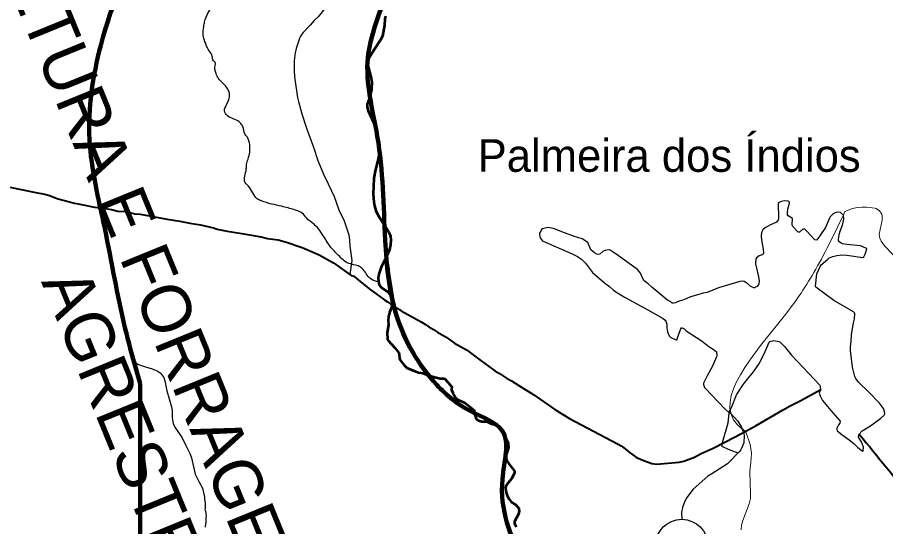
# Model space of a CAD drawing. Extents: x -1643653 to 4543381, y 1624270 to 13878484.
# Drawn here: x 748641 to 761950, y 8955606 to 8963412 of the extents above; entities that cross this region are included whole.
import ezdxf
from ezdxf.enums import TextEntityAlignment as Align

# ---------------------------------------------------------------- set-up
doc = ezdxf.new("R2010")
doc.units = 0
doc.header["$LTSCALE"] = 200
for name, color, linetype, lineweight in [('12', 7, 'Continuous', 25), ('14', 7, 'Continuous', 13), ('21', 7, 'Continuous', 25), ('24', 7, 'Continuous', 25), ('26', 7, 'Continuous', 106), ('28', 7, 'Continuous', 53), ('48', 7, 'Continuous', 25), ('60', 7, 'Continuous', 13), ('9', 7, 'Continuous', 90)]:
    doc.layers.add(name, color=color, linetype=linetype, lineweight=lineweight)
doc.layers.add('41', color=7, linetype='Continuous')
doc.layers.add('42', color=7, linetype='Continuous')

msp = doc.modelspace()

# ---------------------------------------------------------------- linework, layer by layer
at = {"layer": '12'}
for points in [[(753459.3, 8963663.9), (753375.2, 8963570.6), (753254.1, 8963422.1), (753189.6, 8963361.6), (753131.1, 8963293.6), (753017.7, 8963172.8), (752982.1, 8963123.5), (752970.7, 8963101.1), (752914.6, 8962932.2), (752900.9, 8962868.1), (752884.4, 8962747.8), (752884.2, 8962579.2), (752893.6, 8962459.8), (752918.2, 8962289)], [(752918.2, 8962289), (752933.3, 8962184.9), (752947.7, 8962120.1), (752999.2, 8961934.7), (753071.9, 8961715.6), (753180.7, 8961424), (753248.1, 8961217.1), (753248.1, 8961217.1), (753333.6, 8961006.6), (753405.8, 8960861.1), (753494.8, 8960666.1), (753525.5, 8960579.3)], [(753525.5, 8960579.3), (753567.3, 8960461.2), (753647.9, 8960293.1), (753719.6, 8960078), (753729.9, 8960000.8), (753736.5, 8959906), (753766.3, 8959686.5), (753736.3, 8959470.4)], [(759689.9, 8956732.7), (759543.3, 8956787), (759453.4, 8956827.9), (759441.1, 8956839.4), (759450.5, 8956898), (759538.2, 8957195.8), (759549.6, 8957346.3), (759553.3, 8957357.9), (759571, 8957344.3), (759680.6, 8957229.9), (759737, 8957142.1), (759777.6, 8957031.5), (759780.6, 8957004.8), (759774.7, 8956889.8), (759729.9, 8956785.1), (759706.9, 8956753.4), (759526.3, 8956568.6), (759344.8, 8956450.4), (759284.8, 8956417.4), (759226.1, 8956377.1), (758999, 8956178.4), (758931.1, 8956094.6), (758894, 8956037.2), (758861.3, 8955972.4), (758835.9, 8955899.8), (758821.1, 8955826.8), (758825.4, 8955718.1)]]:
    msp.add_lwpolyline(points, dxfattribs=at)
at = {"layer": '12', "lineweight": 40}
for points in [[(747824.8, 8960950.1), (748696.8, 8960775.7), (748951, 8960720.9), (749061.5, 8960701.6), (749146.4, 8960677), (749208.9, 8960650.1), (749264.1, 8960631.6), (749514.7, 8960562.8), (749573.6, 8960554.1), (749824.1, 8960500.3), (749993.7, 8960480.2), (750082, 8960465.4), (750181.5, 8960442.6), (750295.8, 8960435.7), (750443.2, 8960399.6), (750522, 8960394.7), (750939.1, 8960317.4), (751130.9, 8960287.1), (751285.6, 8960255.2), (751447.8, 8960232), (751646.7, 8960184), (751702.1, 8960166.7), (751856.8, 8960132.2), (752079.6, 8960098.7), (752168.1, 8960083)], [(752168.1, 8960083), (752376.2, 8960046), (752473.7, 8960024.1), (752636.8, 8960000.4), (752768, 8959966), (753007.9, 8959884.9), (753265, 8959774.4), (753487.3, 8959648.4), (753758.2, 8959455.5), (753784.2, 8959450.7), (753798.9, 8959443.4), (753866.8, 8959388.1)], [(753866.8, 8959388.1), (754029.7, 8959255.4), (754273.1, 8959074.6), (754315.3, 8959050.4), (754424.8, 8958977.4), (754499, 8958935.4), (754521.9, 8958913.6), (754830.4, 8958745.4), (754896.1, 8958704.8), (754948.1, 8958666.3), (755022.1, 8958627.1), (755080.2, 8958588.1), (755212.9, 8958510.5), (755342.6, 8958419.2), (755526.8, 8958316.3), (755751.2, 8958147.5)], [(755751.2, 8958147.5), (755862.2, 8958064), (755958, 8957996.2), (756032.6, 8957954.2), (756137.7, 8957884), (756214, 8957842.6), (756328.1, 8957767.5), (756559.2, 8957627.5), (756879.8, 8957401.3), (757104, 8957264.6), (757287.1, 8957167.7), (757840.4, 8956875)], [(759805, 8957070.3), (759963.8, 8957157.4), (760368.2, 8957393.4), (760487, 8957457.4), (760649.4, 8957537.9), (760959, 8957710.3)], [(757840.4, 8956875), (757898, 8956844.5), (757957.3, 8956800.7), (758017.3, 8956746), (758132.8, 8956665.6), (758252.6, 8956612), (758364.7, 8956572), (758441.3, 8956562.7), (758786.4, 8956593.9), (758858.3, 8956611.9), (759022.3, 8956672.3), (759120.5, 8956724.4), (759308, 8956809.8), (759644.5, 8956982.5), (759805, 8957070.3)]]:
    msp.add_lwpolyline(points, dxfattribs=at)
msp.add_spline([(761549.2, 8957020.4), (762383.1, 8955993.9), (763257, 8954902.9), (764214.4, 8953717.3), (766168.2, 8951324.4), (767086.6, 8950171.6), (770317.8, 8946184.2), (771971, 8944146), (773006.3, 8942876.2), (773223.4, 8942642.3), (773373.7, 8942274.8), (774008.3, 8940921.5), (774359, 8940136.3), (774475.8, 8939919.1), (774642.8, 8939785.5), (774893.3, 8939668.5), (775511.2, 8939484.7), (775928.6, 8939267.5), (776078.9, 8939184), (776379.5, 8938916.7), (776680.1, 8938749.6), (776830.4, 8938582.6), (777398.1, 8938348.7), (777899.1, 8938231.7), (778550.4, 8938482.3), (779134.8, 8938866.6), (779452.1, 8939250.8), (779569, 8939384.5), (779685.9, 8939351.1), (779852.9, 8939217.4), (780086.7, 8939217.4), (780604.3, 8939451.3), (781055.2, 8939618.4), (781439.3, 8939618.4), (781823.3, 8939518.1), (782090.5, 8939401.2), (782290.9, 8939367.8), (782524.7, 8939518.1), (782858.7, 8939618.4), (783192.6, 8939651.8), (783509.9, 8939818.9), (783910.7, 8940119.6), (784278.1, 8940336.8), (784625.2, 8940434.5)], degree=3, dxfattribs=at)
at = {"layer": '14'}
for points in [[(762539, 8959785.5), (762526.5, 8959782.1), (762447.5, 8959737.2), (762371.9, 8959688.1), (762188, 8959687.4), (762169, 8959695.8), (762058.2, 8959775.3), (761932.6, 8959909.4), (761880.9, 8959981.3), (761863.6, 8960025), (761852.7, 8960090.2), (761896.3, 8960301.7), (761898.2, 8960370.1), (761891.8, 8960394.3), (761858.6, 8960446.3), (761803.1, 8960482.1), (761785, 8960487.6), (761657.6, 8960503.3), (761588.8, 8960503.3), (761520, 8960497.3), (761442.8, 8960481.4), (761326.7, 8960433.8), (761317.3, 8960424.7), (761303.1, 8960378.2)], [(759805, 8957070.3), (759809.7, 8957060.9), (759876.2, 8956866.7), (759896, 8956733.5), (759886, 8956587.7), (759873.4, 8956514.6), (759867.3, 8956445.9), (759879.8, 8956106.2), (759877.3, 8956037.4), (759858.6, 8955956.3), (759761.5, 8955697.4), (759741.8, 8955628.8), (759734.4, 8955555.9)]]:
    msp.add_lwpolyline(points, dxfattribs=at)
msp.add_spline([(761326.7, 8960433.8), (760878.8, 8959550), (760374.9, 8958805.9), (759682, 8957166.3), (759809.7, 8957060.9)], degree=3, dxfattribs=at)
at = {"layer": '21'}
for points in [[(760406.9, 8960599.4), (760351.2, 8960587.4), (760306.3, 8960567.9), (760304.1, 8960553.3), (760309.9, 8960343.7), (760307.6, 8960319.4), (760302.3, 8960306.5), (760277, 8960272.3), (760173.9, 8960227.9), (760102, 8960186.9), (760066.3, 8960155.5), (760048.5, 8960114.9), (760043.8, 8960055.7), (760047.2, 8959999.8), (760070.9, 8959859.8), (760077.3, 8959796.6), (760071.9, 8959782.9), (760055.5, 8959771.5), (760010.4, 8959755.9), (759970.5, 8959727.7), (759962.7, 8959712), (759957.3, 8959636.2), (760000.3, 8959433.2), (760011.1, 8959366.6), (760007.5, 8959329.7), (759980.1, 8959288.4), (759957.5, 8959276), (759943.8, 8959263.8), (759943.8, 8959263.8), (759931.4, 8959264.6), (759884.8, 8959286.2), (759838.1, 8959329.8), (759780.4, 8959363), (759763.1, 8959366.1), (759715.1, 8959363.1), (759387.5, 8959268.5), (759215.8, 8959195.5), (759154.3, 8959182.2), (759089.3, 8959164.5)], [(761303.1, 8960378.2), (761256.6, 8960420.7), (761211, 8960424.4), (761189, 8960420), (761148.3, 8960398.4), (761101, 8960352.7), (761089.5, 8960334.7), (761027.1, 8960191.2), (760943.1, 8960062.8), (760896.2, 8960002.8), (760882, 8959997.4), (760865.7, 8960003.5), (760853.2, 8960013.2), (760749.8, 8960127.6), (760712.2, 8960164.5), (760701.2, 8960167.6), (760679.8, 8960164.2), (760632.4, 8960121), (760616.8, 8960117.8), (760603.7, 8960126.1), (760526.3, 8960205.6), (760516.4, 8960233.9), (760520.7, 8960327.1), (760483.2, 8960353), (760453.9, 8960367.2), (760443.7, 8960384.1), (760443.7, 8960422.2), (760450.8, 8960474.1), (760476.4, 8960562.9), (760474.8, 8960577.8), (760467.9, 8960589.4), (760454.3, 8960595.3), (760406.9, 8960599.4)], [(761456.2, 8958896.2), (761158.8, 8959073.4), (760923.1, 8959244.1), (760881.8, 8959278.4), (760874.4, 8959292.7), (760897, 8959480.3), (760948.2, 8959595.3), (760963.9, 8959617.7), (761063.1, 8959703.5), (761082.5, 8959724.5), (761142.1, 8959747.5), (761202.2, 8959763.2), (761279.4, 8959770.2), (761356.4, 8959765.7), (761602.1, 8959732.9), (761613.8, 8959740.5), (761636.1, 8959780.9), (761661.5, 8959862.7), (761646.6, 8959874.6), (761567.3, 8959909.9), (761356.6, 8959929.5), (761288, 8959941.5), (761269.3, 8959950.7), (761230.4, 8959983.8), (761227.4, 8960000.2), (761237.8, 8960082), (761258.1, 8960151), (761288.7, 8960228.4), (761310.4, 8960320.3), (761303.1, 8960378.2)], [(757025.3, 8960111), (756856.9, 8960173.6), (756774.4, 8960189), (756690.4, 8960169.5), (756676.8, 8960159.2), (756667.8, 8960142.8)], [(756667.8, 8960142.8), (756646.1, 8960103.2), (756641.9, 8960082.9), (756655.4, 8960034.6), (756685.1, 8959993.4), (756700.1, 8959979.2), (757143.4, 8959788.8), (757225.5, 8959744.8), (757292.5, 8959702.4), (757351, 8959642), (757458.4, 8959500.5), (757638.5, 8959341.8), (757717.9, 8959284.2), (757774.1, 8959233.8), (757815.6, 8959204.4), (757958.2, 8959117.6), (758306, 8958929.9), (758539.4, 8958798.4), (758570.9, 8958770.5), (758581.6, 8958755.2), (758594, 8958710.9), (758597.7, 8958651.4), (758608.3, 8958591.8), (758630.7, 8958530.3), (758658.3, 8958506.6), (758722.6, 8958472.6), (758739.5, 8958467.4), (758749.1, 8958469.2), (758804.9, 8958627.7), (758819.6, 8958652.9), (758832.5, 8958653.7), (758862.6, 8958638.9), (758895.1, 8958607.2), (759137.6, 8958446.3), (759240.8, 8958367.8), (759305.9, 8958326.1), (759355.4, 8958284.4), (759361.1, 8958229.7), (759356.1, 8958207.5), (759296.4, 8958064.8), (759214.4, 8957916.7), (759160.7, 8957806.5), (759158.7, 8957795.2)], [(757384.3, 8959963), (757296.5, 8960017), (757165.6, 8960058.9), (757025.3, 8960111)], [(759089.3, 8959164.5), (758959.7, 8959128.9), (758856.5, 8959082.7), (758786.4, 8959061), (758729.8, 8959035.8), (758696.2, 8959030.6), (758679.5, 8959033.6), (758657.5, 8959052.8), (758608.3, 8959079.4), (758549.1, 8959121.3), (758427, 8959226.7), (758365.1, 8959274.5), (758308.6, 8959327.6), (758250.8, 8959371), (758222.4, 8959421.7), (758194.1, 8959488.8), (758147.7, 8959547.5), (757819.2, 8959780.1), (757726.2, 8959841.5), (757701.7, 8959847.4), (757651.1, 8959840.7), (757620.3, 8959829.3), (757571.8, 8959784.6), (757543.6, 8959777.7), (757522.3, 8959779.8), (757486.6, 8959802), (757431.8, 8959850.2), (757384.3, 8959963)], [(761460.2, 8958729), (761471.4, 8958793.2), (761478, 8958868), (761475.3, 8958881.2), (761456.2, 8958896.2)], [(761699.8, 8957660.8), (761534.4, 8957820.5), (761494.3, 8957876.1), (761476.7, 8957908.7), (761441.7, 8958050.3), (761410.2, 8958307.4), (761410.3, 8958367.7), (761421.6, 8958439.5), (761428.9, 8958549.5), (761460.2, 8958729)], [(759588.1, 8957430.5), (759665.6, 8957627.1), (759774.1, 8957789.3), (759851, 8957889.6), (759926.4, 8957977.2), (760019.3, 8958109.5), (760103.6, 8958290.5), (760163.1, 8958434.3), (760177, 8958444.1), (760236, 8958459.9), (760236, 8958459.9), (760311.5, 8958445.7), (760328.1, 8958437.3), (760399.4, 8958368.9), (760505.5, 8958234.5), (760941.1, 8957774.4), (760949.2, 8957754.5), (760953.1, 8957699.6), (760934.3, 8957666.8), (760932.5, 8957654.1), (760946.9, 8957611.2), (760983.8, 8957536.8), (761107.8, 8957384.2), (761255, 8957220.4), (761250.7, 8957192.7), (761230.3, 8957168.3), (761203.2, 8957115.4), (761200.8, 8957095.3), (761208, 8957075.8), (761277.5, 8957017.6), (761412.8, 8956919.4), (761466, 8956875.3), (761523.6, 8956817.2), (761588.2, 8956767.8), (761600.9, 8956762.8), (761607.8, 8956766.9), (761610.8, 8956824.1), (761578.4, 8956906.9), (761533.3, 8956976.3), (761532.5, 8956989.4), (761545, 8957020.8), (761589.6, 8957073.6), (761719.9, 8957149.7), (761874.4, 8957269.1), (761925.5, 8957315.7), (761936.7, 8957332.9), (761927.8, 8957389.9), (761916.5, 8957416.7), (761854.4, 8957499), (761699.8, 8957660.8)], [(759158.7, 8957795.2), (759156.5, 8957782.8), (759174.7, 8957739.3), (759187.4, 8957722), (759486.6, 8957410.7), (759541.3, 8957360.2), (759547, 8957358.6), (759554, 8957364.5), (759569.1, 8957391.3), (759588.1, 8957430.5)]]:
    msp.add_lwpolyline(points, dxfattribs=at)
at = {"layer": '24', "lineweight": 53}
for points in [[(754285.7, 8963432), (754273.9, 8963387.1), (754266, 8963290.7), (754236.9, 8963123.5), (754201.7, 8963057.3), (754114.6, 8962926), (754027.8, 8962785.2), (754016.9, 8962748.7), (754010.6, 8962674.3), (754066.2, 8962478), (754076.2, 8962418.6), (754066.8, 8962303.7), (754054.9, 8962239.9), (754034.7, 8962164.2), (754002.5, 8962083.6), (754003.6, 8962036.3), (754018, 8961976.9), (754099.6, 8961801.3), (754131.9, 8961713.6), (754174.2, 8961542.5), (754191.4, 8961398.6), (754193.2, 8961347.2), (754168.7, 8961215.5), (754129.2, 8961079.8), (754106, 8960948.1), (754094.1, 8960701.2), (754103.1, 8960586), (754113, 8960522.2)], [(754113, 8960522.2), (754133.2, 8960450.2), (754164.6, 8960385.9), (754285.4, 8960201), (754333.3, 8960119.1), (754358.5, 8960059.1), (754366.7, 8960003.6), (754361.1, 8959927.4), (754342.9, 8959851.5), (754312.2, 8959776.4), (754218.7, 8959583.9), (754182.3, 8959476.4), (754169.4, 8959412.5), (754180.9, 8959330), (754188.6, 8959309.7), (754216.4, 8959278.5), (754249.1, 8959251.2), (754317.6, 8959205.1), (754378.4, 8959135.3), (754396.6, 8959107.3), (754395.3, 8959068.2), (754385.8, 8959005.2), (754369.7, 8958949.7), (754345.2, 8958889.9), (754331, 8958822.6), (754326, 8958771), (754328.4, 8958699.2), (754310.7, 8958580.2), (754315.6, 8958473.5), (754326.5, 8958456.4), (754433.4, 8958343.3), (754486.5, 8958269.1), (754495.6, 8958248.3), (754500.9, 8958184.1), (754506.9, 8958158.4), (754569.5, 8958079.4), (754610.9, 8958038.6)], [(754610.9, 8958038.6), (754610.9, 8958038.6), (754731.2, 8957987.7), (754791.1, 8957970), (754854.6, 8957958.1), (754922.6, 8957930.3), (755038.2, 8957895.5), (755123.8, 8957875.9), (755185.9, 8957875.1)], [(755185.9, 8957875.1), (755238.8, 8957821.3), (755295.4, 8957755.3), (755298.8, 8957744.7), (755293, 8957714.3), (755295, 8957700.2), (755316.4, 8957655.1), (755359, 8957583.6), (755405.6, 8957545), (755497.6, 8957501.2), (755563.5, 8957459.9), (755635.5, 8957398.1), (755644, 8957381.6), (755650.3, 8957338.2), (755674.1, 8957259.6), (755682.8, 8957247.8), (755709.3, 8957231.1), (755761.1, 8957215.6), (755838.8, 8957216.3), (755909.4, 8957183.9), (755979.1, 8957165.2)], [(755979.1, 8957165.2), (756099.8, 8957011.9), (756133.3, 8956953.6), (756164.7, 8956883.8)], [(756164.7, 8956883.8), (756167.7, 8956814.9), (756135.2, 8956708.9), (756132.8, 8956661.9), (756136.2, 8956626.4), (756187.9, 8956545.8), (756252.7, 8956472.7), (756258.8, 8956454.4), (756261.3, 8956424.2), (756215.1, 8956340.9), (756146.2, 8956251.2), (756128.1, 8956221.2), (756124, 8956199.7), (756128.2, 8956143.1), (756146.9, 8956084.8), (756173.9, 8956031), (756217.2, 8955981.5), (756283.3, 8955940.1), (756321.8, 8955893.7), (756329.4, 8955877.8), (756331.8, 8955847), (756324.5, 8955795.2), (756263.6, 8955684.9), (756259.8, 8955654.5), (756286.7, 8955604.2)]]:
    msp.add_lwpolyline(points, dxfattribs=at)
at = {"layer": '24'}
for points in [[(754285.7, 8963432), (754273.9, 8963387.1), (754266, 8963290.7), (754236.9, 8963123.5), (754201.7, 8963057.3), (754114.6, 8962926), (754027.8, 8962785.2), (754016.9, 8962748.7), (754010.6, 8962674.3), (754066.2, 8962478), (754076.2, 8962418.6), (754066.8, 8962303.7), (754054.9, 8962239.9), (754034.7, 8962164.2), (754002.5, 8962083.6), (754003.6, 8962036.3), (754018, 8961976.9), (754099.6, 8961801.3), (754131.9, 8961713.6), (754174.2, 8961542.5), (754191.4, 8961398.6), (754193.2, 8961347.2), (754168.7, 8961215.5), (754129.2, 8961079.8), (754106, 8960948.1), (754094.1, 8960701.2), (754103.1, 8960586), (754113, 8960522.2)], [(754113, 8960522.2), (754133.2, 8960450.2), (754164.6, 8960385.9), (754285.4, 8960201), (754333.3, 8960119.1), (754358.5, 8960059.1), (754366.7, 8960003.6), (754361.1, 8959927.4), (754342.9, 8959851.5), (754312.2, 8959776.4), (754218.7, 8959583.9), (754182.3, 8959476.4), (754169.4, 8959412.5), (754180.9, 8959330), (754188.6, 8959309.7), (754216.4, 8959278.5), (754249.1, 8959251.2), (754317.6, 8959205.1), (754378.4, 8959135.3), (754396.6, 8959107.3), (754395.3, 8959068.2), (754385.8, 8959005.2), (754369.7, 8958949.7), (754345.2, 8958889.9), (754331, 8958822.6), (754326, 8958771), (754328.4, 8958699.2), (754310.7, 8958580.2), (754315.6, 8958473.5), (754326.5, 8958456.4), (754433.4, 8958343.3), (754486.5, 8958269.1), (754495.6, 8958248.3), (754500.9, 8958184.1), (754506.9, 8958158.4), (754569.5, 8958079.4), (754610.9, 8958038.6)], [(750423.6, 8958135.7), (750499.6, 8958092.9), (750602.7, 8958055.6), (750709.5, 8958026.2), (750782, 8957991.5), (750830.2, 8957961.5), (750855.2, 8957933.6), (750884.2, 8957892.1), (750902.2, 8957841), (750932.8, 8957688.1), (751002.6, 8957440.2), (751011.1, 8957385.5), (751012.3, 8957279.8), (751029.1, 8957185.3), (751054.7, 8957130.6), (751168.1, 8956969), (751218.5, 8956860.1), (751291.5, 8956717.4), (751311.6, 8956662.7), (751365.8, 8956411.3), (751423, 8956298.1), (751477.7, 8956195.2), (751505.7, 8956084.4)], [(754610.9, 8958038.6), (754610.9, 8958038.6), (754731.2, 8957987.7), (754791.1, 8957970), (754854.6, 8957958.1), (754922.6, 8957930.3), (755038.2, 8957895.5), (755123.8, 8957875.9), (755185.9, 8957875.1)], [(755185.9, 8957875.1), (755238.8, 8957821.3), (755295.4, 8957755.3), (755298.8, 8957744.7), (755293, 8957714.3), (755295, 8957700.2), (755316.4, 8957655.1), (755359, 8957583.6), (755405.6, 8957545), (755497.6, 8957501.2), (755563.5, 8957459.9), (755635.5, 8957398.1), (755644, 8957381.6), (755650.3, 8957338.2), (755674.1, 8957259.6), (755682.8, 8957247.8), (755709.3, 8957231.1), (755761.1, 8957215.6), (755838.8, 8957216.3), (755909.4, 8957183.9), (755979.1, 8957165.2)], [(755979.1, 8957165.2), (756099.8, 8957011.9), (756133.3, 8956953.6), (756164.7, 8956883.8)], [(756164.7, 8956883.8), (756167.7, 8956814.9), (756135.2, 8956708.9), (756132.8, 8956661.9), (756136.2, 8956626.4), (756187.9, 8956545.8), (756252.7, 8956472.7), (756258.8, 8956454.4), (756261.3, 8956424.2), (756215.1, 8956340.9), (756146.2, 8956251.2), (756128.1, 8956221.2), (756124, 8956199.7), (756128.2, 8956143.1), (756146.9, 8956084.8), (756173.9, 8956031), (756217.2, 8955981.5), (756283.3, 8955940.1), (756321.8, 8955893.7), (756329.4, 8955877.8), (756331.8, 8955847), (756324.5, 8955795.2), (756263.6, 8955684.9), (756259.8, 8955654.5), (756286.7, 8955604.2)], [(751505.7, 8956084.4), (751507.4, 8956055.1), (751508.1, 8956042.7), (751510.5, 8956026.3), (751513.5, 8956003.2), (751520.2, 8955965.6), (751521.6, 8955957.9), (751521.9, 8955951.5), (751522.8, 8955950.1)], [(751520.4, 8955950.1), (751521.7, 8955924.3), (751521.1, 8955909.7), (751519.5, 8955892.5), (751517.2, 8955883.6), (751515.1, 8955868.8), (751519.1, 8955855.6), (751523.6, 8955846.3), (751529.6, 8955801.9), (751533.5, 8955770.7), (751531.2, 8955742.9), (751527.4, 8955706), (751527.1, 8955688.9), (751529, 8955674), (751525.8, 8955639.9), (751521.3, 8955611.7), (751519.4, 8955598.1)]]:
    msp.add_lwpolyline(points, dxfattribs=at)
msp.add_spline([(754168.1, 8959356.7), (754118.5, 8959373.3), (754015.9, 8959439.5), (753963, 8959522.3), (753920, 8959565.3), (753863.7, 8959601.7), (753777.7, 8959624.9), (753671.8, 8959664.6), (753599, 8959727.5), (753470, 8959860), (753347.6, 8960035.4), (753188.7, 8960240.7), (753072.9, 8960336.7), (753006.8, 8960409.6), (752887.7, 8960462.5), (752692.4, 8960515.5), (752381.4, 8960598.3), (752318.6, 8960631.4), (752182.9, 8960823.4), (752133.3, 8960879.7), (752149.8, 8961088.3), (752153.1, 8961154.5), (752176.3, 8961240.6), (752202.8, 8961346.5), (752202.8, 8961459.1), (752163.1, 8961578.2), (752126.7, 8961627.9), (752100.2, 8961730.6), (752067.1, 8961783.5), (752020.8, 8961823.2), (751842.1, 8961922.6), (751815.6, 8962002), (751828.9, 8962035.1), (751891.7, 8962194.1), (751891.7, 8962247), (751799.1, 8962392.7), (751723, 8962475.5), (751686.6, 8962551.6), (751673.4, 8962674.1), (751680, 8962710.5), (751646.7, 8962746), (751629.2, 8962814.3), (751582.4, 8962896.2), (751541.5, 8962972.3), (751516.1, 8963036.6), (751490.8, 8963138), (751498.6, 8963270.7), (751510.3, 8963338.9), (751566.8, 8963485.2), (751623.3, 8963580.8), (751638.9, 8963627.6), (751638.9, 8963670.5), (751613.6, 8963762.2), (751561, 8963914.3), (751555.1, 8963990.3), (751566.8, 8964163.9), (751545.4, 8964241.9), (751500.6, 8964314.1), (751401.2, 8964419.4), (751358.3, 8964503.3), (751350.5, 8964659.3), (751381.7, 8964780.2), (751408.9, 8964864.1), (751405, 8964942.1), (751391.4, 8965002.6), (751327.1, 8965100.1), (751223.8, 8965226.9), (751149.7, 8965359.5), (751110.7, 8965523.3), (751102.9, 8965618.9), (751071.8, 8965913.4), (751038.6, 8966215.7), (751023, 8966471), (751017.2, 8966644)], degree=3, dxfattribs=at)
at = {"layer": '26'}
msp.add_spline([(738865.3, 8967422.1), (739557.2, 8967298.3), (740701.8, 8967013.8), (741413.3, 8966731.2), (743000.3, 8965872.6), (743559.1, 8965590.5), (744439.9, 8965968.4), (745374, 8966727.6), (746233.2, 8967779.5), (746809, 8968247.7), (747844.5, 8968942.9), (749056.2, 8969268.5), (750229.7, 8969581.6), (752050.8, 8969574.1), (752518.4, 8968949.1), (753046.2, 8967700.6), (754351.7, 8964009.2), (754013.3, 8962799.9), (754158.3, 8961590.6), (754279.2, 8959994.3), (754448.4, 8958857.5), (755069.1, 8957779.3), (755600.9, 8957368.1), (756072.3, 8957077.8), (756075.9, 8956332), (756399.8, 8955071.7), (756665.8, 8954671.3), (757824.9, 8954152.2), (758684.7, 8953765.2), (759807.2, 8953486.2), (759964.3, 8952494.5), (759785.3, 8951475.9), (759658.7, 8951007.7), (759460.5, 8950660.7), (759411.1, 8950095.7), (759130.3, 8949726.7), (759168.8, 8949567), (759377.9, 8949449), (759532.1, 8949168), (759383.5, 8948839.9), (759243.4, 8946764.2), (759236.6, 8946560.6)], degree=3, dxfattribs=at)
at = {"layer": '28'}
for points in [[(754422.8, 8958978.7), (754279.2, 8959994.3), (754158.3, 8961590.6), (754013.3, 8962799.9), (754351.7, 8964009.2), (753190.3, 8967338.5)], [(757632.6, 8954238.4), (756665.8, 8954671.3), (756399.8, 8955071.7), (756075.9, 8956332), (756072.3, 8957077.8), (755600.9, 8957368.1), (755069.1, 8957779.3), (754448.4, 8958857.5), (754422.8, 8958978.7)]]:
    msp.add_spline(points, degree=3, dxfattribs=at)
at = {"layer": '48'}
msp.add_circle((758825.5, 8955317.1), 401.3, dxfattribs=at)
at = {"layer": '60', "lineweight": 25}
msp.add_spline([(814781, 9009175.5), (814787.2, 9009173.4), (814796.9, 9009173.4), (814799.4, 9009172.4), (814805.1, 9009174.5), (814805.6, 9009176.5), (814811.7, 9009179.5), (814811.7, 9009179.5), (814801.5, 9009181), (814790.7, 9009181.5), (814784.1, 9009183.1), (814777.4, 9009185.1), (814778.4, 9009175.5)], degree=3, dxfattribs=at)
at = {"layer": '9'}
msp.add_lwpolyline([(737921.5, 8948812.5), (740981.3, 8950253.8), (750519.5, 8951321.2), (750521.5, 8957798.6)], dxfattribs=at)
msp.add_spline([(750521.5, 8957798.6), (750290, 8958657.6), (749980, 8960173.9), (749746.6, 8961538.9), (749919.1, 8962982.1), (750673.6, 8964858.9), (751354.2, 8966153.2), (751832.9, 8967092.2), (752515.2, 8967905.8), (752689.9, 8968716.5), (752991.6, 8969502.6), (753167.8, 8969908.5), (753010.5, 8971299.2), (753439.5, 8973954.2)], degree=3, dxfattribs=at)

# ---------------------------------------------------------------- texts
at = {"layer": '41'}
msp.add_text('Palmeira dos Índios', height=500, dxfattribs=at).set_placement((755696.3, 8961044.2))
at = {"layer": '42'}
for s, p in [('FRUTICULTURA E FORRAGEIRA (BOVINOS) IRRIGADA', (751782.1, 8955862.9)), ('AGRESTE NORTE', (750625, 8955389.9))]:
    msp.add_text(s, height=750, rotation=292.237, dxfattribs=at).set_placement(p, align=Align.CENTER)

doc.saveas('drawing.dxf')
